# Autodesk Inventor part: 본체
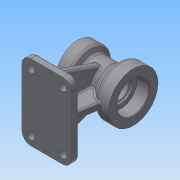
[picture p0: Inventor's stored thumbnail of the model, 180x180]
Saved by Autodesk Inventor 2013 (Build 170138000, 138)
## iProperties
Created: 2015-08
Part Number: 본체
Material: 일반
Document SubType Name: Modeling
Designer: Administrator
Density: 1 g/cm^3
Author: Administrator
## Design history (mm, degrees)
sketch "스케치1"
  geometry: L1 (0, 0)-(90, 0); L2 (0, 0)-(0, 35); L3 (0, 35)-(20, 35); L4 (20, 35)-(25.196, 26); L5 (25.196, 26)-(53.315, 26); L6 (53.315, 26)-(70, 40); L7 (70, 40)-(90, 40); L8 (90, 40)-(90, 0)
  constraints: 16 end point, 3 parallel, 2 perpendicular, 1 horizontal
  dimensions: "d0" = 90 distance of L1.start L1.end; "d1" = 20 distance of L2.end L3.end; "d3" = 70 diameter of L3 L1; "d4" = 80 diameter of L7 L1; "d5" = 40 deg angle of L5 L6; "d6" = 60 deg angle of L5 L4; "d7" = 20 distance of L6.end L7.end; "d8" = 52 diameter of L5 L1
revolve "회전1" sketch "스케치1" stored, may be unused: angle "d9" = 90 deg
sketch "스케치2"
  geometry: L1 (0, -78)-(80, -78); L2 (80, -78)-(80, -90); L3 (80, -90)-(0, -90); L4 (0, -90)-(0, -78); 1 further point
  constraints: 8 end point, 2 parallel, 1 horizontal, 1 perpendicular, 1 vertical alignment
  dimensions: "d10" = 12 distance of L1.end L2.end; "d12" = 80 distance of L2.end L3.end; "d13" = 90 distance from line of L3 point (0, 0)
extrude "돌출1" join sketch "스케치2" stored distance "d14" = 122; taper "d15" = 0 deg
sketch "스케치3"
  geometry: L1 (0, -35)-(0, 35) reference; L2 (0, 35)-(20, 35) reference; L3 (20, 35)-(25.196, 26) reference; L4 (25.196, 26)-(53.315, 26) reference; L5 (53.315, 26)-(70, 40) reference; L6 (70, 40)-(90, 40) reference; L7 (90, 40)-(90, -40) reference; L8 (90, -40)-(70, -40) reference; L9 (70, -40)-(53.315, -26) reference; L10 (53.315, -26)-(25.196, -26) reference; L11 (25.196, -26)-(20, -35) reference; L12 (20, -35)-(0, -35) reference; L13 (80, -78)-(80, -90) reference; L14 (80, -90)-(0, -90) reference; L15 (0, -90)-(0, -78) reference; L16 (0, -78)-(80, -78) reference; L17 (10, -78)-(10, -35); L18 (70, -78)-(76.7, -40); 1 further point
  constraints: 4 end point, 3 point on line, 1 midpoint
  dimensions: "d16" = 10 distance from line of L17 L15.end; "d19" = 80 deg angle of L16 L18; "d20" = 10 distance from line of L13 L18.start
  node "절단 모서리 투영1"
node "작업 평면1"
sketch "스케치4"
  geometry: L1 (-78, -61)-(-90, -61) reference; L2 (-90, -61)-(-90, 61) reference; L3 (-90, 61)-(-78, 61) reference; L4 (-78, 61)-(-78, -61) reference; L5 (-78, -51)-(-6.815, -25.091); L6 (-78, 51)-(-6.815, 25.091); A1 r 26 centre (0, 0) between (-6.815, -25.091) and (-6.815, 25.091) reference; 1 further point
  constraints: 4 end point, 2 point on circle, 2 point on line
  dimensions: "d113" = 10 distance from line of L1 L5.start; "d114" = 70 deg angle of L5 L4; "d115" = 10 distance from line of L6.start L3; "d116" = 70 deg angle of L4 L6
extrude "돌출2" join sketch "스케치4" stored distance "d24" = 12; taper "d25" = 0 deg
feature "리브1" dims "d26" = 1, "d27" = 12, "d28" = 0, "d29" = 0, "d30" = 1, "d31" = 1
feature "리브2" dims "d32" = 1, "d33" = 12, "d34" = 0, "d35" = 0, "d36" = 1, "d37" = 1
hole "구멍1" diameter "d40" = 38; stored, may be unused: countersink angle "d44" = 90 deg, drill point angle "d46" = 0 deg; dims "d41" = 6, "d42" = 52, "d43" = 20, "d45" = 23, "d47" = 10, "d48" = 10
hole "구멍2" diameter "d51" = 32; stored, may be unused: countersink angle "d55" = 90 deg, drill point angle "d57" = 118 deg; dims "d49" = 10, "d50" = 10, "d52" = 6, "d53" = 40, "d54" = 17, "d56" = 23
sketch "스케치5"
  geometry: C1 r 26 at (0, 0) reference; 1 further point
  constraints: 1 vertical alignment
  dimensions: "d58" = 33 distance of C1.centre point (0, 33)
hole "구멍3" sketch "스케치5" at (0, 33) diameter "d59" = 3.242; stored, may be unused: countersink angle "d63" = 90 deg, drill point angle "d65" = 118 deg; dims "d60" = 10, "d61" = 40, "d62" = 17, "d64" = 13
sketch "스케치6"
  geometry: C1 r 20 at (0, 0) reference; 1 further point
  constraints: 1 vertical alignment
  dimensions: "d69" = 27 distance of C1.centre point (0, 27)
hole "구멍4" sketch "스케치6" at (0, 27) diameter "d70" = 3.242; stored, may be unused: countersink angle "d74" = 90 deg, drill point angle "d76" = 118 deg; dims "d71" = 10, "d72" = 40, "d73" = 17, "d75" = 13
sketch "스케치7"
  geometry: L1 (6, -25.298)-(6, -78) reference; L2 (51, -78)-(6, -78) reference; L3 (-61, -78)-(-51, -78) reference; L4 (-51, -78)-(-6, -78) reference; L5 (-6, -78)-(-6, -25.298) reference; L6 (-61, -90)-(-61, -78) reference; L7 (61, -90)-(-61, -90) reference; L8 (61, -78)-(61, -90) reference; L9 (51, -78)-(61, -78) reference; L10 (6, -25.298)-(6, -78) reference; L11 (18, -54)-(18, -60); L12 (30, -54)-(30, -60); L13 (-51, -78)-(-25.091, -6.815) reference; L14 (6, -78)-(51, -78) reference; L15 (25.091, -6.815)-(51, -78) reference; C1 r 16 at (0, 0) reference; A1 r 6 centre (24, -54) between (30, -54) and (18, -54); A2 r 6 centre (24, -60) between (18, -60) and (30, -60); A3 r 26 centre (0, 0) between (-25.091, -6.815) and (-6, -25.298) reference; A4 r 26 centre (0, 0) between (6, -25.298) and (25.091, -6.815) reference; A5 r 26 centre (0, 0) between (25.091, -6.815) and (-25.091, -6.815) reference
  constraints: 4 end point, 4 point on circle, 3 tangent, 2 centre point, 1 parallel, 1 vertical alignment
  dimensions: "d80" = 12 diameter of A1; "d81" = 12 diameter of A2; "d82" = 18 dimension on A2 A1; "d83" = 18 distance from line of A2.centre L2; "d84" = 24 horizontal distance of A2.centre C1.centre
extrude "돌출3" cut sketch "스케치7" stored distance "d85" = 12; taper "d86" = 0 deg
fillet "모깎기1" dims "d87" = 14
sketch "스케치8"
  geometry: C1 r 6 at (52, 14); C2 r 6 at (0, 14); C3 r 6 at (0, 108); C4 r 6 at (52, 108); A1 r 14 centre (0, 14) between (-14, 14) and (0, 0) reference; A2 r 14 centre (52, 14) between (52, 0) and (66, 14) reference; A3 r 14 centre (52, 108) between (66, 108) and (52, 122) reference; A4 r 14 centre (0, 108) between (0, 122) and (-14, 108) reference; 1 further point
  constraints: 4 centre point, 4 coincident
  dimensions: "d88" = 12 diameter of C1; "d90" = 12 diameter of C2; "d91" = 12 diameter of C3; "d92" = 12 diameter of C4
extrude "돌출4" cut sketch "스케치8" stored distance "d93" = 12; taper "d94" = 0 deg
sketch "스케치9"
  geometry: L1 (0, 0)-(0, 43.518) reference; L2 (-10, 0)-(4, 0) reference; L3 (-10, -12)-(-10, 0) reference; 2 further points
  constraints: 1 other
  dimensions: "d95" = 24 distance from line of point (16, 24) L2; "d97" = 16 distance from line of point (16, 24) L1
feature "엠보싱1" sketch "스케치9" dims "d0" = 90, "d1" = 20, "d3" = 70, "d4" = 80, "d5" = 40 deg, "d6" = 60 deg, "d7" = 20, "d8" = 52, "d98" = 0.5, "d99" = 0
fillet "모깎기2" dims "d100" = 5
fillet "모깎기3" dims "d101" = 0.3
fillet "모깎기4" dims "d102" = 3
chamfer "모따기1" distance "d103" = 1; stored, may be unused: second distance "d104" = 2, angle "d105" = 45 deg
fillet "모깎기5" dims "d106" = 3
fillet "모깎기8" dims "d109" = 3
fillet "모깎기9" dims "d117" = 3
fillet "모깎기10" dims "d118" = 3
node "솔리드1"
pattern_circular "원형 패턴1" dims angle "d67" = 360 deg
pattern_circular "원형 패턴2" dims angle "d78" = 360 deg
mirror "대칭1"
node "작업 평면2"
node "절단 모서리 투영2"
node "절단 모서리 투영3"
